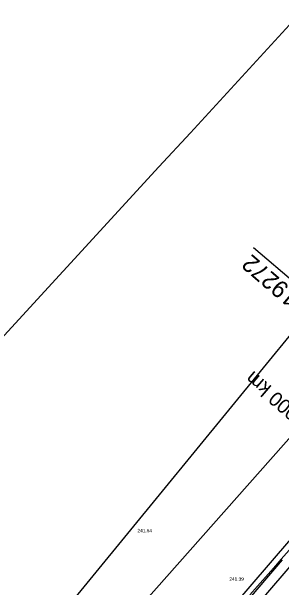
# Model space of a CAD drawing. Extents: x -555887 to -552101, y -1100251 to -1096546.
# Drawn here: x -555051.9 to -555004.7, y -1097790.6 to -1097689.9 of the extents above; entities that cross this region are included whole.
import ezdxf

# ---------------------------------------------------------------- set-up
doc = ezdxf.new("R2010")
doc.units = 0
for name, color, linetype in [('IP_návrh', 7, 'Continuous'), ('PARCELY_cesty', 7, 'Continuous'), ('PARCELY_ZP', 7, 'Continuous'), ('POLYGONY_SITUACE_PF_POPISY', 7, 'Continuous'), ('POLYGONY_SITUACE_PO', 7, 'Continuous'), ('Výškopis', 7, 'Continuous'), ('zájem', 7, 'Continuous')]:
    doc.layers.add(name, color=color, linetype=linetype)

msp = doc.modelspace()

# ---------------------------------------------------------------- linework, layer by layer
msp.add_line((-554993.6, -1097745), (-555009.59, -1097731.24))
at = {"layer": 'IP_návrh'}
msp.add_lwpolyline([(-555730.85, -1098494.64), (-555471.29, -1098211.98), (-555447.19, -1098191.79), (-555406.99, -1098193.78), (-555291.32, -1098130.27), (-555281.27, -1098119.66), (-555272.34, -1098101.41), (-555266.18, -1098052.11), (-555246.83, -1098023.92), (-555193.03, -1097978.41), (-554985.79, -1097744.7), (-554956.17, -1097701), (-554939.23, -1097656.04), (-554918.86, -1097601.97), (-554899.16, -1097585.1)], dxfattribs=at)
at = {"layer": 'PARCELY_cesty'}
msp.add_lwpolyline([(-554890.98, -1097593.9), (-554905.31, -1097608.08), (-554909.68, -1097613.07), (-554913.54, -1097618.63), (-554917.4, -1097626.58), (-554942.61, -1097692.28), (-554947.4, -1097703.77), (-554955.89, -1097720.43), (-554962.25, -1097731.07), (-554972.89, -1097746.45), (-554980.74, -1097756.11), (-555043.66, -1097829.27), (-555070.96, -1097860.03)], dxfattribs=at)
at = {"layer": 'PARCELY_ZP'}
msp.add_lwpolyline([(-555084.65, -1097845.81), (-554996.25, -1097738.07), (-554991.41, -1097732.44), (-554975.72, -1097715.14), (-554969.48, -1097701.5), (-554963.22, -1097681.7), (-554956.79, -1097665.5), (-554948.77, -1097647.97), (-554934.81, -1097617.66)], dxfattribs=at)
at = {"layer": 'POLYGONY_SITUACE_PO'}
for p, q in [((-554978.43, -1097758.04), (-555041.41, -1097831.25)), ((-555003.39, -1097784.1), (-555004.76, -1097785.66)), ((-555004.76, -1097785.66), (-555006.13, -1097787.23)), ((-555004.61, -1097785.79), (-555005.97, -1097787.37)), ((-555006.13, -1097787.23), (-555007.51, -1097788.79)), ((-555005.97, -1097787.37), (-555007.33, -1097788.95)), ((-555007.51, -1097788.79), (-555008.89, -1097790.35)), ((-555007.33, -1097788.95), (-555008.69, -1097790.53)), ((-555008.89, -1097790.35), (-555010.27, -1097791.91)), ((-555008.69, -1097790.53), (-555010.05, -1097792.11))]:
    msp.add_line(p, q, dxfattribs=at)
at = {"layer": 'zájem'}
for points in [[(-554588.14, -1097239.01), (-554733.55, -1097399.26), (-554743.08, -1097409.76), (-554775.75, -1097445.72), (-554786.65, -1097457.7), (-554793.53, -1097465.36), (-554864.78, -1097543.87), (-554885.93, -1097567.08), (-554889.29, -1097569.68), (-554893.97, -1097573.72), (-554896.43, -1097575.85), (-554902.44, -1097582.45), (-554917.04, -1097598.33), (-554934.81, -1097617.66), (-554945.09, -1097628.87), (-554957.3, -1097642.21), (-554970.1, -1097656.1), (-554982.25, -1097669.37), (-554994.97, -1097683.15), (-555020.64, -1097711.13), (-555026.18, -1097717.1), (-555075.78, -1097771.09)], [(-555075.78, -1097771.09), (-555026.18, -1097717.1), (-555020.64, -1097711.13), (-554994.97, -1097683.15), (-554982.25, -1097669.37), (-554970.1, -1097656.1), (-554957.3, -1097642.21), (-554945.09, -1097628.87), (-554934.81, -1097617.66), (-554917.04, -1097598.33), (-554902.44, -1097582.45), (-554896.43, -1097575.85), (-554893.97, -1097573.72), (-554889.29, -1097569.68), (-554885.93, -1097567.08), (-554864.78, -1097543.87), (-554793.53, -1097465.36), (-554786.65, -1097457.7), (-554775.75, -1097445.72), (-554743.08, -1097409.76), (-554733.55, -1097399.26), (-554588.14, -1097239.01)]]:
    msp.add_lwpolyline(points, dxfattribs=at)

# ---------------------------------------------------------------- texts
msp.add_text('KT 0.19272', height=3, rotation=139.2985).set_placement((-554994.25, -1097745.75))
at = {"layer": 'POLYGONY_SITUACE_PF_POPISY'}
msp.add_text('0.21000 km', height=2.5, rotation=139.2985, dxfattribs=at).set_placement((-554996.44, -1097764.02))
at = {"layer": 'Výškopis'}
for s, p in [('241.64', (-555029.9, -1097780.96)), ('241.39', (-555013.84, -1097789.43))]:
    msp.add_text(s, height=0.6, dxfattribs=at).set_placement(p)

doc.saveas('drawing.dxf')
